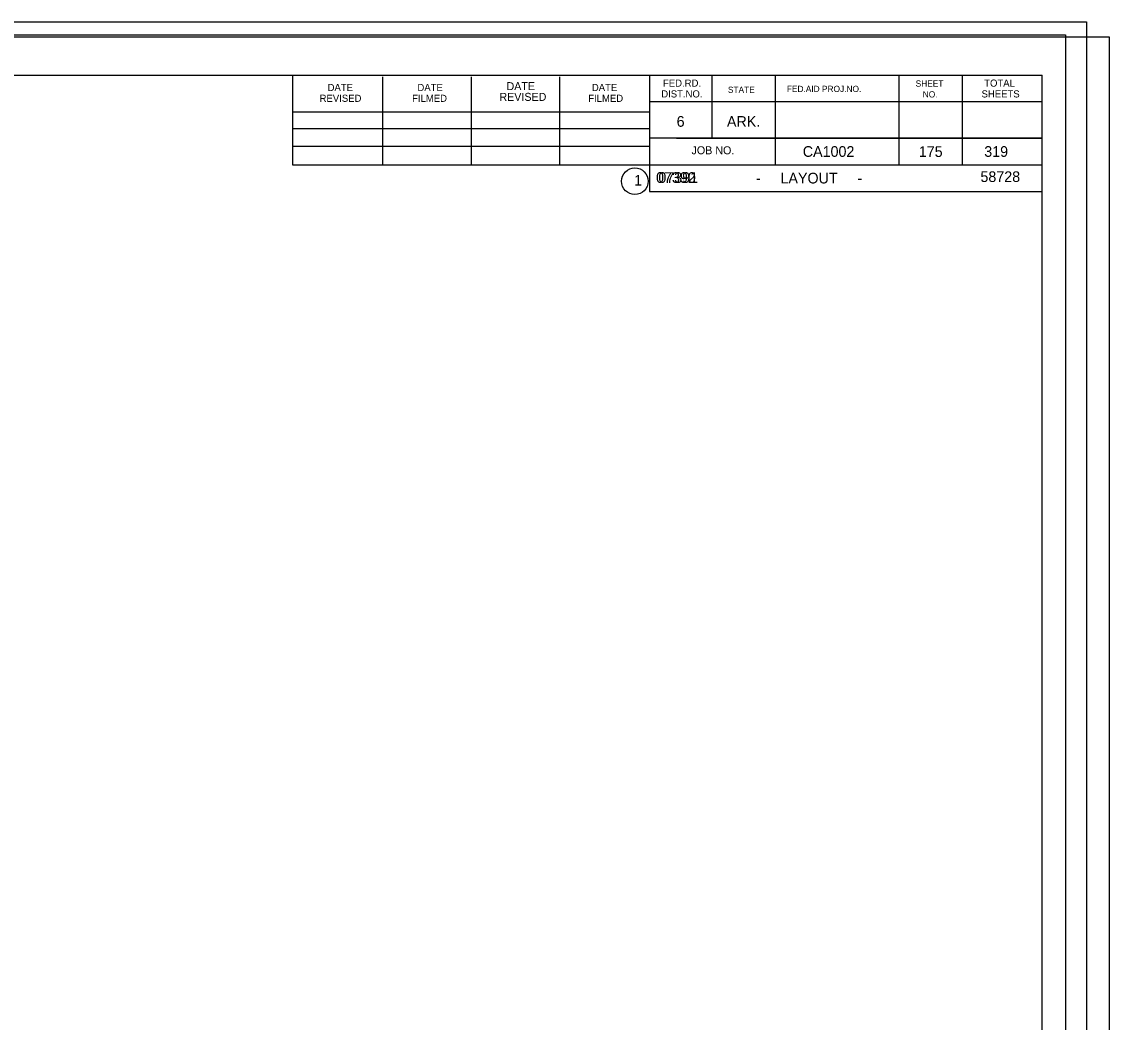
# Model space of a CAD drawing. Extents: x -40 to 1219, y 101 to 761.
# Drawn here: x 636.3 to 994.6, y 431 to 760.7 of the extents above; entities that cross this region are included whole.
import ezdxf

# ---------------------------------------------------------------- set-up
doc = ezdxf.new("R2010")
doc.units = 0
for name, color, linetype in [('border', 7, 'Continuous'), ('Border 2660-Hwy18 - Level 62', 7, 'Continuous'), ('Border 2660-Hwy18 - Level 63', 7, 'Continuous'), ('Border 2660-Hwy18 - Text', 7, 'Continuous'), ('Bridge No BLFR', 7, 'Continuous'), ('Bridge No BLO', 7, 'Continuous'), ('Bridge No Ditch 81', 7, 'Continuous'), ('Level 62 PDF', 7, 'Continuous'), ('Text', 7, 'Continuous'), ('Title Text', 7, 'Continuous')]:
    doc.layers.add(name, color=color, linetype=linetype)

msp = doc.modelspace()

# ---------------------------------------------------------------- linework, layer by layer
at = {"layer": 'border'}
for p, q in [((12.1, 743.11), (972.44, 743.11)), ((725.66, 713.48), (725.66, 743.11)), ((755.21, 713.48), (755.21, 742.53)), ((784.52, 713.48), (784.52, 742.53)), ((813.53, 713.48), (813.53, 742.53)), ((843.12, 743.11), (843.12, 704.73)), ((863.64, 743.11), (863.64, 722.3)), ((884.49, 743.11), (884.49, 713.48)), ((925.2, 743.11), (925.2, 713.48)), ((946.05, 743.11), (946.05, 713.48)), ((972.44, 126.75), (972.44, 743.11)), ((725.66, 731.05), (843.12, 731.05)), ((972.44, 734.29), (843.12, 734.29)), ((972.44, 734.36), (972.44, 734.36)), ((725.66, 725.47), (843.12, 725.47)), ((972.44, 722.3), (843.12, 722.3)), ((852.02, 722.3), (972.44, 722.3)), ((725.66, 713.48), (725.66, 719.67)), ((725.66, 719.67), (843.12, 719.67)), ((972.44, 713.48), (725.66, 713.48)), ((843.12, 704.73), (972.44, 704.73))]:
    msp.add_line(p, q, dxfattribs=at)
msp.add_circle((838.29, 708.13), 4.4, dxfattribs=at)
at = {"layer": 'Border 2660-Hwy18 - Level 62'}
msp.add_lwpolyline([(-36.5, 760.68), (987.05, 760.68), (987.05, 106.39), (-36.5, 106.39)], close=True, dxfattribs=at)
at = {"layer": 'Border 2660-Hwy18 - Level 63'}
msp.add_lwpolyline([(-39.83, 756.39), (980.15, 756.39), (980.15, 115.31), (-39.83, 115.31)], close=True, dxfattribs=at)
at = {"layer": 'Level 62 PDF'}
msp.add_lwpolyline([(-29, 755.68), (994.55, 755.68), (994.55, 101.39), (-29, 101.39)], close=True, dxfattribs=at)

# ---------------------------------------------------------------- texts
at = {"layer": 'Border 2660-Hwy18 - Text'}
for s, height, p in [('FED.RD.', 2.345, (847.55, 739.29)), ('TOTAL', 2.345, (953.36, 739.29)), ('DATE', 2.345, (737.07, 737.85)), ('DATE', 2.345, (766.66, 737.85)), ('DATE', 2.637, (796, 738.14)), ('DATE', 2.345, (824.12, 737.85)), ('DIST.NO.', 2.345, (846.98, 735.73)), ('STATE', 2.052, (868.94, 737.24)), ('FED.AID PROJ.NO.', 2.0516, (888.34, 737.53)), ('SHEET', 2.052, (930.78, 739.29)), ('SHEETS', 2.345, (952.49, 735.73)), ('REVISED', 2.345, (734.44, 734.29)), ('FILMED', 2.345, (764.9, 734.29)), ('REVISED', 2.637, (793.66, 734.61)), ('FILMED', 2.345, (822.93, 734.29)), ('NO.', 2.052, (933.12, 735.73)), ('6', 3.52, (852.05, 726.08)), ('ARK.', 3.516, (868.61, 726.08)), ('JOB NO.', 2.637, (856.95, 717.01)), ('CA1002', 3.516, (893.6, 716.17)), ('319', 3.516, (953.38, 716.17)), ('1', 3.51, (838.07, 706.71))]:
    msp.add_text(s, height=height, dxfattribs=at).set_placement(p)
at = {"layer": 'Bridge No BLFR'}
msp.add_text('07392', height=3.516, dxfattribs=at).set_placement((845.26, 707.59))
at = {"layer": 'Bridge No BLO'}
msp.add_text('07391', height=3.516, dxfattribs=at).set_placement((846.03, 707.59))
at = {"layer": 'Bridge No Ditch 81'}
msp.add_text('07390', height=3.516, dxfattribs=at).set_placement((845.28, 707.59))
at = {"layer": 'Text'}
msp.add_text('175', height=3.516, dxfattribs=at).set_placement((931.82, 716.14))
at = {"layer": 'Title Text'}
for s, height, p in [('-     LAYOUT     -', 3.5167, (878.16, 707.4)), ('58728', 3.517, (952.12, 707.88))]:
    msp.add_text(s, height=height, dxfattribs=at).set_placement(p)

doc.saveas('drawing.dxf')
